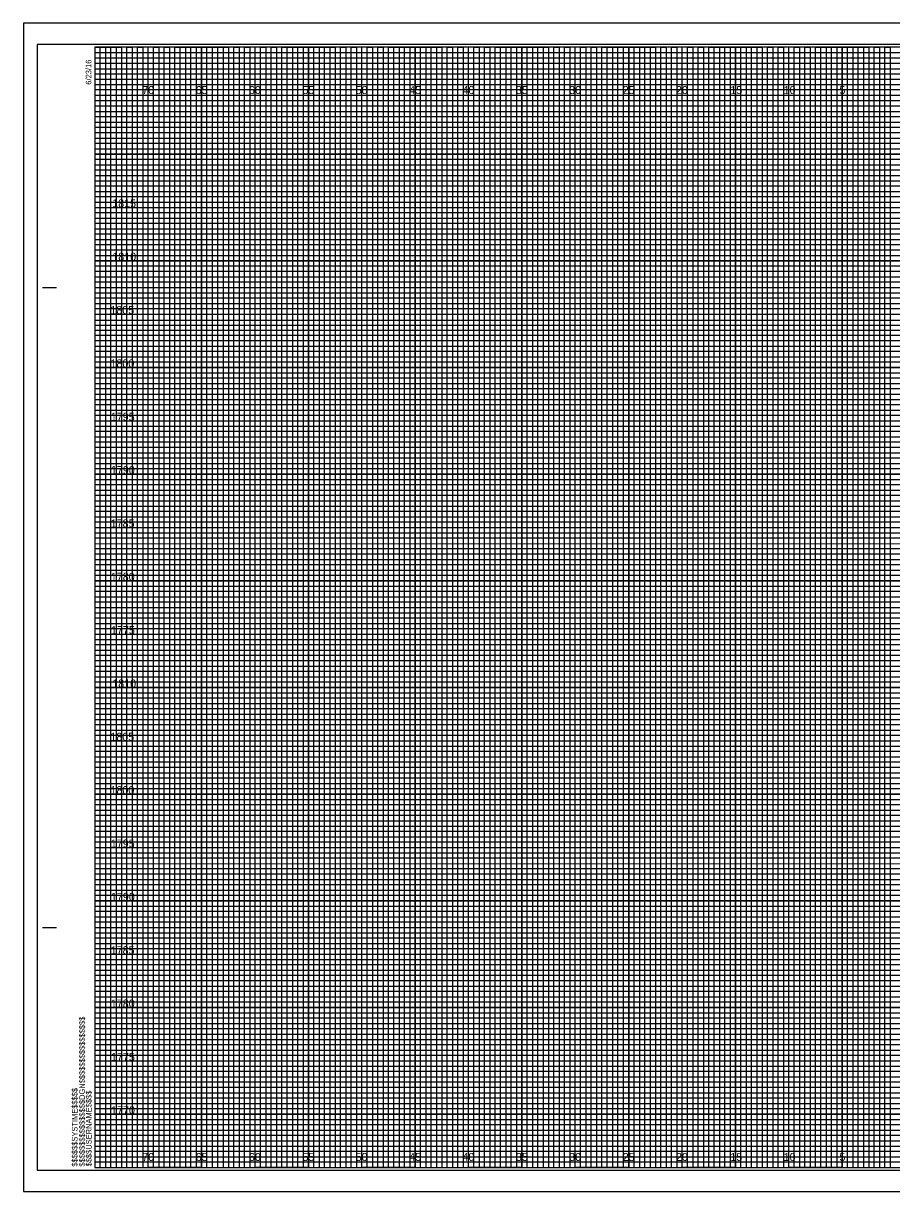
# Model space of a CAD drawing. Extents: x 346 to 514, y -13 to 537.
# Drawn here: x 346 to 427.4, y 207.2 to 316.7 of the extents above; entities that cross this region are included whole.
import ezdxf

# ---------------------------------------------------------------- set-up
doc = ezdxf.new("R2010")
doc.units = 0
for name, color, linetype in [('COGO Default Curve', 7, 'Continuous'), ('Prop Horizontal Alignment', 7, 'Continuous'), ('Prop XS DDE', 7, 'Continuous'), ('Scratch_Level_3', 7, 'Continuous'), ('Sheet Cross Section CELL', 7, 'Continuous'), ('Sheet Cross Section Grid Minor 1 CELL', 7, 'Continuous'), ('Sheet Cross Section Grid Minor 2 CELL', 7, 'Continuous'), ('Sheet Cutting Line CELL', 7, 'Continuous'), ('Sheet DOT Grid CELL', 7, 'Continuous'), ('Sheet Plot Border Inside CELL', 7, 'Continuous'), ('Sheet Plot Border Outside CELL', 7, 'Continuous')]:
    doc.layers.add(name, color=color, linetype=linetype)

msp = doc.modelspace()

# ---------------------------------------------------------------- linework, layer by layer
at = {"layer": 'COGO Default Curve'}
for points in [[(352.75, 314.43), (355.25, 314.43), (355.25, 209.43), (360.25, 209.43), (360.25, 314.43), (365.25, 314.43), (365.25, 209.43), (370.25, 209.43), (370.25, 314.43), (375.25, 314.43), (375.25, 209.43), (380.25, 209.43), (380.25, 314.43), (385.25, 314.43), (385.25, 209.43), (390.25, 209.43), (390.25, 314.43), (395.25, 314.43), (395.25, 209.43), (400.25, 209.43), (400.25, 314.43), (405.25, 314.43), (405.25, 209.43), (410.25, 209.43), (410.25, 314.43), (415.25, 314.43), (415.25, 209.43), (420.25, 209.43), (420.25, 314.43), (425.25, 314.43), (425.25, 209.43), (430.25, 209.43)], [(352.75, 311.93), (490.25, 311.93)], [(352.75, 301.93), (512.75, 301.93), (512.75, 306.93), (352.75, 306.93)], [(352.75, 291.93), (512.75, 291.93), (512.75, 296.93), (352.75, 296.93)], [(352.75, 281.93), (512.75, 281.93), (512.75, 286.93), (352.75, 286.93)], [(352.75, 271.93), (512.75, 271.93), (512.75, 276.93), (352.75, 276.93)], [(352.75, 261.93), (512.75, 261.93), (512.75, 266.93), (352.75, 266.93)], [(352.75, 251.93), (512.75, 251.93), (512.75, 256.93), (352.75, 256.93)], [(352.75, 241.93), (512.75, 241.93), (512.75, 246.93), (352.75, 246.93)], [(352.75, 231.93), (512.75, 231.93), (512.75, 236.93), (352.75, 236.93)], [(352.75, 221.93), (512.75, 221.93), (512.75, 226.93), (352.75, 226.93)], [(352.75, 211.93), (512.75, 211.93), (512.75, 216.93), (352.75, 216.93)]]:
    msp.add_lwpolyline(points, dxfattribs=at)
at = {"layer": 'Prop XS DDE'}
for p, q in [((357.75, 314.43), (352.75, 314.43)), ((357.75, 209.43), (357.75, 314.43)), ((367.75, 314.43), (362.75, 314.43)), ((362.75, 314.43), (362.75, 209.43)), ((367.75, 209.43), (367.75, 314.43)), ((377.75, 314.43), (372.75, 314.43)), ((372.75, 314.43), (372.75, 209.43)), ((377.75, 209.43), (377.75, 314.43)), ((387.75, 314.43), (382.75, 314.43)), ((382.75, 314.43), (382.75, 209.43)), ((387.75, 209.43), (387.75, 314.43)), ((397.75, 314.43), (392.75, 314.43)), ((392.75, 314.43), (392.75, 209.43)), ((397.75, 209.43), (397.75, 314.43)), ((407.75, 314.43), (402.75, 314.43)), ((402.75, 314.43), (402.75, 209.43)), ((407.75, 209.43), (407.75, 314.43)), ((417.75, 314.43), (412.75, 314.43)), ((412.75, 314.43), (412.75, 209.43)), ((417.75, 209.43), (417.75, 314.43)), ((427.75, 314.43), (422.75, 314.43)), ((422.75, 314.43), (422.75, 209.43)), ((362.75, 209.43), (357.75, 209.43)), ((372.75, 209.43), (367.75, 209.43)), ((382.75, 209.43), (377.75, 209.43)), ((392.75, 209.43), (387.75, 209.43)), ((402.75, 209.43), (397.75, 209.43)), ((412.75, 209.43), (407.75, 209.43)), ((422.75, 209.43), (417.75, 209.43))]:
    msp.add_line(p, q, dxfattribs=at)
for points in [[(352.75, 309.43), (512.75, 309.43), (512.75, 304.43), (352.75, 304.43)], [(352.75, 299.43), (512.75, 299.43), (512.75, 294.43), (352.75, 294.43)], [(352.75, 289.43), (512.75, 289.43), (512.75, 284.43), (352.75, 284.43)], [(352.75, 279.43), (512.75, 279.43), (512.75, 274.43), (352.75, 274.43)], [(352.75, 269.43), (512.75, 269.43), (512.75, 264.43), (352.75, 264.43)], [(352.75, 259.43), (512.75, 259.43), (512.75, 254.43), (352.75, 254.43)], [(352.75, 249.43), (512.75, 249.43), (512.75, 244.43), (352.75, 244.43)], [(352.75, 239.43), (512.75, 239.43), (512.75, 234.43), (352.75, 234.43)], [(352.75, 229.43), (512.75, 229.43), (512.75, 224.43), (352.75, 224.43)], [(352.75, 219.43), (512.75, 219.43), (512.75, 214.43), (352.75, 214.43)]]:
    msp.add_lwpolyline(points, dxfattribs=at)
at = {"layer": 'Sheet Cross Section CELL'}
for p, q in [((347.85, 291.93), (349.1, 291.93)), ((347.9, 291.93), (349.15, 291.93)), ((347.85, 231.93), (349.1, 231.93)), ((347.9, 231.93), (349.15, 231.93)), ((352.75, 209.43), (352.75, 209.43)), ((352.75, 209.43), (352.75, 209.43)), ((352.75, 209.43), (352.75, 209.43)), ((352.75, 209.43), (352.75, 209.43)), ((352.75, 209.43), (352.75, 209.43)), ((352.75, 209.43), (352.75, 209.43)), ((352.75, 209.43), (352.75, 209.43))]:
    msp.add_line(p, q, dxfattribs=at)
msp.add_lwpolyline([(512.75, 314.43), (352.75, 314.43), (352.75, 209.43), (512.75, 209.43)], close=True, dxfattribs=at)
at = {"layer": 'Sheet Cross Section Grid Minor 1 CELL'}
for p, q in [((352.75, 313.93), (482.75, 313.93)), ((482.75, 313.42), (352.75, 313.42)), ((352.75, 313.42), (352.75, 312.93)), ((352.75, 312.93), (482.75, 312.93)), ((482.75, 312.37), (352.75, 312.37)), ((352.75, 312.37), (352.75, 311.43)), ((352.75, 311.43), (512.75, 311.43))]:
    msp.add_line(p, q, dxfattribs=at)
for points in [[(352.75, 310.93), (487.75, 310.93), (512.75, 310.93), (512.75, 310.43), (352.75, 310.43)], [(352.75, 309.93), (512.75, 309.93), (512.75, 308.93), (352.75, 308.93)], [(352.75, 308.43), (512.75, 308.43), (512.75, 307.93), (352.75, 307.92)], [(352.75, 307.43), (512.75, 307.43), (512.75, 306.43), (352.75, 306.43)], [(352.75, 305.93), (512.75, 305.93), (512.75, 305.43), (352.75, 305.43)], [(352.75, 304.93), (512.75, 304.93), (512.75, 303.93), (352.75, 303.93)], [(352.75, 303.43), (512.75, 303.43), (512.75, 302.93), (352.75, 302.93)], [(352.75, 302.43), (512.75, 302.43), (512.75, 301.43), (352.75, 301.43)], [(352.75, 300.93), (512.75, 300.93), (512.75, 300.43), (352.75, 300.43)], [(352.75, 299.93), (512.75, 299.93), (512.75, 298.93), (352.75, 298.93)], [(352.75, 298.43), (512.75, 298.43), (512.75, 297.93), (352.75, 297.93)], [(352.75, 297.43), (512.75, 297.43), (512.75, 296.4), (512.75, 295.93), (512.75, 295.43), (352.75, 295.43)], [(352.75, 296.43), (512.75, 296.43), (512.75, 295.93), (352.75, 295.93)], [(352.75, 294.93), (512.75, 294.93), (512.75, 293.93), (352.75, 293.94)], [(352.75, 293.94), (512.75, 293.93), (512.75, 293.43), (352.75, 293.43)], [(352.75, 292.93), (512.75, 292.93), (512.75, 292.43), (352.75, 292.43)], [(352.75, 291.43), (512.75, 291.43), (512.75, 290.93), (352.75, 290.93)], [(352.75, 290.43), (512.75, 290.43), (512.75, 289.93), (352.75, 289.93)], [(352.71, 288.87), (512.75, 288.87), (512.75, 288.37), (352.71, 288.37)], [(352.75, 287.93), (512.75, 287.93), (512.75, 287.43), (352.75, 287.43)], [(352.75, 286.43), (512.75, 286.43), (512.75, 285.93), (352.75, 285.93)], [(352.75, 285.43), (512.75, 285.43), (512.75, 284.93), (352.75, 284.93)], [(352.75, 283.93), (512.75, 283.93), (512.75, 283.43), (352.75, 283.43)], [(352.75, 282.93), (512.75, 282.93), (512.75, 282.43), (352.75, 282.43)], [(352.75, 281.43), (512.75, 281.43), (512.75, 280.93), (352.75, 280.93)], [(352.75, 280.43), (512.75, 280.43), (512.75, 279.93), (352.75, 279.93)], [(352.75, 278.93), (512.75, 278.93), (512.74, 278.42), (352.75, 278.43)], [(352.75, 277.93), (512.75, 277.93), (512.75, 277.43), (352.75, 277.43)], [(352.75, 276.43), (512.75, 276.43), (512.75, 275.93), (352.75, 275.93)], [(352.75, 275.43), (512.75, 275.43), (512.75, 274.93), (352.75, 274.93)], [(352.75, 273.93), (512.75, 273.93), (512.75, 273.43), (352.75, 273.43)], [(352.75, 272.93), (512.75, 272.93), (512.75, 272.43), (352.75, 272.43)], [(352.75, 271.43), (512.75, 271.43), (512.75, 270.93), (352.75, 270.93)], [(352.75, 270.43), (512.75, 270.43), (512.75, 269.93), (352.75, 269.93)], [(352.75, 268.93), (512.75, 268.93), (512.75, 268.43), (352.75, 268.43)], [(352.75, 267.92), (512.78, 267.88), (512.75, 267.43), (352.75, 267.43)], [(352.75, 266.43), (512.75, 266.43), (512.75, 265.93), (352.75, 265.93)], [(352.75, 265.43), (512.75, 265.43), (512.75, 264.93), (352.75, 264.93)], [(352.75, 263.93), (512.75, 263.93), (512.75, 263.43), (352.75, 263.43)], [(352.75, 262.93), (512.75, 262.93), (512.75, 262.43), (352.75, 262.43)], [(352.75, 261.43), (512.75, 261.43), (512.75, 260.93), (352.75, 260.93)], [(352.75, 260.43), (512.75, 260.43), (512.75, 259.93), (352.75, 259.93)], [(352.75, 258.93), (512.75, 258.93), (512.75, 258.43), (352.75, 258.43)], [(352.75, 257.93), (512.75, 257.93), (512.75, 257.43), (352.75, 257.43)], [(352.75, 256.43), (512.75, 256.43), (512.75, 255.93), (352.75, 255.93)], [(352.75, 255.43), (512.75, 255.43), (512.75, 254.93), (352.75, 254.93)], [(352.75, 253.93), (512.75, 253.93), (512.75, 253.43), (352.75, 253.43)], [(352.75, 252.93), (512.75, 252.93), (512.75, 252.43), (352.75, 252.43)], [(352.75, 251.43), (512.75, 251.43), (512.75, 250.93), (352.75, 250.93)], [(352.75, 250.43), (512.75, 250.43), (512.75, 249.93), (352.75, 249.93)], [(352.75, 248.93), (512.75, 248.93), (512.74, 248.42), (352.75, 248.43)], [(352.75, 247.93), (512.75, 247.93), (512.75, 247.43), (352.75, 247.43)], [(352.75, 246.43), (512.75, 246.43), (512.75, 245.93), (352.75, 245.93)], [(352.75, 245.43), (512.75, 245.43), (512.75, 244.93), (352.75, 244.93)], [(352.75, 243.93), (512.75, 243.93), (512.75, 243.43), (352.75, 243.43)], [(352.75, 242.93), (512.75, 242.93), (512.75, 242.43), (352.75, 242.43)], [(352.75, 241.43), (512.75, 241.43), (512.75, 240.93), (352.75, 240.93)], [(352.75, 240.43), (512.75, 240.43), (512.75, 239.93), (352.75, 239.93)], [(352.75, 238.93), (512.75, 238.93), (512.75, 238.43), (352.75, 238.43)], [(352.75, 237.92), (512.78, 237.88), (512.75, 237.43), (352.75, 237.43)], [(352.75, 236.43), (512.75, 236.43), (512.75, 235.93), (352.75, 235.93)], [(352.75, 235.43), (512.75, 235.43), (512.75, 234.93), (352.75, 234.93)], [(352.75, 233.93), (512.75, 233.93), (512.75, 233.43), (352.75, 233.43)], [(352.75, 232.93), (512.75, 232.93), (512.75, 232.43), (352.75, 232.43)], [(352.75, 231.43), (512.75, 231.43), (512.75, 230.93), (352.75, 230.93)], [(352.75, 230.43), (512.75, 230.43), (512.75, 229.93), (352.75, 229.93)], [(352.75, 228.93), (512.75, 228.93), (512.75, 228.43), (352.75, 228.43)], [(352.75, 227.93), (512.75, 227.93), (512.75, 227.43), (352.75, 227.43)], [(352.75, 226.43), (512.75, 226.43), (512.75, 225.93), (352.75, 225.93)], [(352.75, 225.43), (512.75, 225.43), (512.75, 224.93), (352.75, 224.93)], [(352.75, 223.93), (512.75, 223.93), (512.75, 223.43), (352.75, 223.43)], [(352.75, 222.93), (512.75, 222.93), (512.75, 222.43), (352.75, 222.43)], [(352.75, 221.43), (512.75, 221.43), (512.75, 220.93), (352.75, 220.93)], [(352.75, 220.43), (512.75, 220.43), (512.75, 219.93), (352.75, 219.93)], [(352.75, 218.93), (512.75, 218.93), (512.75, 218.43), (352.75, 218.43)], [(352.75, 217.93), (512.75, 217.93), (512.75, 217.43), (352.75, 217.43)], [(352.75, 216.43), (512.75, 216.43), (512.75, 215.93), (352.75, 215.93)], [(352.75, 215.43), (512.75, 215.43), (512.75, 214.93), (352.75, 214.93)], [(352.75, 213.93), (512.75, 213.93), (512.75, 213.43), (352.75, 213.43)], [(352.75, 212.93), (512.75, 212.93), (512.75, 212.43), (352.75, 212.43)], [(352.75, 211.43), (512.75, 211.43), (512.75, 210.93), (352.75, 210.93)], [(352.75, 210.43), (512.75, 210.43), (512.75, 209.93), (352.75, 209.93)]]:
    msp.add_lwpolyline(points, dxfattribs=at)
at = {"layer": 'Sheet Cross Section Grid Minor 2 CELL'}
for points in [[(352.75, 209.43), (353.25, 209.43), (353.25, 314.43), (353.75, 314.43), (353.75, 209.43)], [(353.75, 209.43), (354.25, 209.43), (354.25, 314.43), (354.75, 314.43), (354.75, 209.43)], [(355.25, 209.43), (355.75, 209.43), (355.75, 314.43), (356.25, 314.43), (356.25, 209.43)], [(356.25, 209.43), (356.75, 209.43), (356.75, 314.43), (357.25, 314.43), (357.25, 209.43)], [(357.75, 209.43), (358.25, 209.43), (358.25, 314.43), (358.75, 314.43), (358.75, 209.43)], [(358.75, 209.43), (359.25, 209.43), (359.25, 314.43), (359.75, 314.43), (359.75, 209.43)], [(360.25, 209.43), (360.75, 209.43), (360.75, 314.43), (361.25, 314.43), (361.25, 209.43)], [(361.25, 209.43), (361.75, 209.43), (361.75, 314.43), (362.25, 314.43), (362.25, 209.43)], [(362.75, 209.43), (363.25, 209.43), (363.25, 314.43), (363.75, 314.43), (363.75, 209.43)], [(363.75, 209.43), (364.25, 209.43), (364.25, 314.43), (364.75, 314.43), (364.75, 209.43)], [(365.25, 209.43), (365.75, 209.43), (365.75, 314.43), (366.25, 314.43), (366.25, 209.43)], [(366.25, 209.43), (366.75, 209.43), (366.75, 314.43), (367.25, 314.43), (367.25, 209.43)], [(367.75, 209.43), (368.25, 209.43), (368.25, 314.43), (368.75, 314.43), (368.75, 209.43)], [(368.75, 209.43), (369.25, 209.43), (369.25, 314.43), (369.75, 314.43), (369.75, 209.43)], [(370.25, 209.43), (370.75, 209.43), (370.75, 314.43), (371.25, 314.43), (371.25, 209.43)], [(371.25, 209.43), (371.75, 209.43), (371.75, 314.43), (372.25, 314.43), (372.25, 209.43)], [(372.75, 209.43), (373.25, 209.43), (373.25, 314.43), (373.75, 314.43), (373.75, 209.43)], [(373.75, 209.43), (374.25, 209.43), (374.25, 314.43), (374.75, 314.43), (374.75, 209.43)], [(375.25, 209.43), (375.75, 209.43), (375.75, 314.43), (376.25, 314.43), (376.25, 209.43)], [(376.25, 209.43), (376.75, 209.43), (376.75, 314.43), (377.25, 314.43), (377.25, 209.43)], [(377.75, 209.43), (378.25, 209.43), (378.25, 314.43), (378.75, 314.43), (378.75, 209.43)], [(378.75, 209.43), (379.25, 209.43), (379.25, 314.43), (379.75, 314.43), (379.75, 209.43)], [(380.25, 209.43), (380.75, 209.43), (380.75, 314.43), (381.25, 314.43), (381.25, 209.43)], [(381.25, 209.43), (381.75, 209.43), (381.75, 314.43), (382.25, 314.43), (382.25, 209.43)], [(382.75, 209.43), (383.25, 209.43), (383.25, 314.43), (383.75, 314.43), (383.75, 209.43)], [(383.75, 209.43), (384.25, 209.43), (384.25, 314.43), (384.75, 314.43), (384.75, 209.43)], [(385.25, 209.43), (385.75, 209.43), (385.75, 314.43), (386.25, 314.43), (386.25, 209.43)], [(386.25, 209.43), (386.75, 209.43), (386.75, 314.43), (387.25, 314.43), (387.25, 209.43)], [(387.75, 209.43), (388.25, 209.43), (388.25, 314.43), (388.75, 314.43), (388.75, 209.43)], [(388.75, 209.43), (389.25, 209.43), (389.25, 314.43), (389.75, 314.43), (389.75, 209.43)], [(390.25, 209.43), (390.75, 209.43), (390.75, 314.43), (391.25, 314.43), (391.25, 209.43)], [(391.25, 209.43), (391.75, 209.43), (391.75, 314.43), (392.25, 314.43), (392.25, 209.43)], [(392.75, 209.43), (393.25, 209.43), (393.25, 314.43), (393.75, 314.43), (393.75, 209.43)], [(393.75, 209.43), (394.25, 209.43), (394.25, 314.43), (394.75, 314.43), (394.75, 209.43)], [(395.25, 209.43), (395.75, 209.43), (395.75, 314.43), (396.25, 314.43), (396.25, 209.43)], [(396.25, 209.43), (396.75, 209.43), (396.75, 314.43), (397.25, 314.43), (397.25, 209.43)], [(397.75, 209.43), (398.25, 209.43), (398.25, 314.43), (398.75, 314.43), (398.75, 209.43)], [(398.75, 209.43), (399.25, 209.43), (399.25, 314.43), (399.75, 314.43), (399.75, 209.43)], [(400.25, 209.43), (400.75, 209.43), (400.75, 314.43), (401.25, 314.43), (401.25, 209.43)], [(401.25, 209.43), (401.75, 209.43), (401.75, 314.43), (402.25, 314.43), (402.25, 209.43)], [(402.75, 209.43), (403.25, 209.43), (403.25, 314.43), (403.75, 314.43), (403.75, 209.43)], [(403.75, 209.43), (404.25, 209.43), (404.25, 314.43), (404.75, 314.43), (404.75, 209.43)], [(405.25, 209.43), (405.75, 209.43), (405.75, 314.43), (406.25, 314.43), (406.25, 209.43)], [(406.25, 209.43), (406.75, 209.43), (406.75, 314.43), (407.25, 314.43), (407.25, 209.43)], [(407.75, 209.43), (408.25, 209.43), (408.25, 314.43), (408.75, 314.43), (408.75, 209.43)], [(408.75, 209.43), (409.25, 209.43), (409.25, 314.43), (409.75, 314.43), (409.75, 209.43)], [(410.25, 209.43), (410.75, 209.43), (410.75, 314.43), (411.25, 314.43), (411.25, 209.43)], [(411.25, 209.43), (411.75, 209.43), (411.75, 314.43), (412.25, 314.43), (412.25, 209.43)], [(412.75, 209.43), (413.25, 209.43), (413.25, 314.43), (413.75, 314.43), (413.75, 209.43)], [(413.75, 209.43), (414.25, 209.43), (414.25, 314.43), (414.75, 314.43), (414.75, 209.43)], [(415.25, 209.43), (415.75, 209.43), (415.75, 314.43), (416.25, 314.43), (416.25, 209.43)], [(416.25, 209.43), (416.75, 209.43), (416.75, 314.43), (417.25, 314.43), (417.25, 209.43)], [(417.75, 209.43), (418.25, 209.43), (418.25, 314.43), (418.75, 314.43), (418.75, 209.43)], [(418.75, 209.43), (419.25, 209.43), (419.25, 314.43), (419.75, 314.43), (419.75, 209.43)], [(420.25, 209.43), (420.75, 209.43), (420.75, 314.43), (421.25, 314.43), (421.25, 209.43)], [(421.25, 209.43), (421.75, 209.43), (421.75, 314.43), (422.25, 314.43), (422.25, 209.43)], [(422.75, 209.43), (423.25, 209.43), (423.25, 314.43), (423.75, 314.43), (423.75, 209.43)], [(423.75, 209.43), (424.25, 209.43), (424.25, 314.43), (424.75, 314.43), (424.75, 209.43)], [(425.25, 209.43), (425.75, 209.43), (425.75, 314.43), (426.25, 314.43), (426.25, 209.43)], [(426.25, 209.43), (426.75, 209.43), (426.75, 314.43), (427.25, 314.43), (427.25, 209.43)]]:
    msp.add_lwpolyline(points, dxfattribs=at)
at = {"layer": 'Sheet Cutting Line CELL'}
for p, q in [((514.4, 316.68), (346.05, 316.68)), ((346.05, 316.68), (346.05, 207.18)), ((346.05, 207.18), (514.4, 207.18))]:
    msp.add_line(p, q, dxfattribs=at)
at = {"layer": 'Sheet DOT Grid CELL'}
for p, q in [((357.75, 209.43), (357.75, 314.43)), ((362.75, 209.43), (362.75, 314.43)), ((367.75, 209.43), (367.75, 314.43)), ((372.75, 209.43), (372.75, 314.43)), ((377.75, 209.43), (377.75, 314.43)), ((382.75, 209.43), (382.75, 314.43)), ((387.75, 209.43), (387.75, 314.43)), ((392.75, 209.43), (392.75, 314.43)), ((397.75, 209.43), (397.75, 314.43)), ((402.75, 209.43), (402.75, 314.43)), ((407.75, 209.43), (407.75, 314.43)), ((412.75, 209.43), (412.75, 314.43)), ((417.75, 209.43), (417.75, 314.43)), ((422.75, 209.43), (422.75, 314.43)), ((352.75, 309.43), (512.75, 309.43)), ((352.75, 304.43), (512.75, 304.43)), ((352.75, 299.43), (512.75, 299.43)), ((352.75, 294.43), (512.75, 294.43)), ((352.75, 289.43), (512.75, 289.43)), ((352.75, 284.43), (512.75, 284.43)), ((352.75, 279.43), (512.75, 279.43)), ((352.75, 274.43), (512.75, 274.43)), ((352.75, 269.43), (512.75, 269.43)), ((352.75, 264.43), (512.75, 264.43)), ((352.75, 259.43), (512.75, 259.43)), ((352.75, 254.43), (512.75, 254.43)), ((352.75, 249.43), (512.75, 249.43)), ((352.75, 244.43), (512.75, 244.43)), ((352.75, 239.43), (512.75, 239.43)), ((352.75, 234.43), (512.75, 234.43)), ((352.75, 229.43), (512.75, 229.43)), ((352.75, 224.43), (512.75, 224.43)), ((352.75, 219.43), (512.75, 219.43)), ((352.75, 214.43), (512.75, 214.43))]:
    msp.add_line(p, q, dxfattribs=at)
at = {"layer": 'Sheet Plot Border Inside CELL'}
msp.add_lwpolyline([(347.35, 209.18), (513.95, 209.18), (513.95, 314.68), (347.35, 314.68)], close=True, dxfattribs=at)
at = {"layer": 'Sheet Plot Border Outside CELL'}
msp.add_lwpolyline([(346.05, 207.18), (514.4, 207.18), (514.4, 316.68), (346.05, 316.68)], close=True, dxfattribs=at)

# ---------------------------------------------------------------- texts
at = {"layer": 'Prop Horizontal Alignment'}
for s, p in [('1815', (354.37, 299.43)), ('1810', (354.38, 294.43)), ('1805', (354.2, 289.43)), ('1800', (354.21, 284.43)), ('1795', (354.24, 279.43)), ('1790', (354.25, 274.43)), ('1785', (354.23, 269.43)), ('1780', (354.24, 264.43)), ('1775', (354.26, 259.43)), ('1810', (354.38, 254.43)), ('1805', (354.2, 249.43)), ('1800', (354.21, 244.43)), ('1795', (354.24, 239.43)), ('1790', (354.25, 234.43)), ('1785', (354.23, 229.43)), ('1780', (354.24, 224.43)), ('1775', (354.26, 219.43)), ('1770', (354.27, 214.43))]:
    msp.add_text(s, height=0.75, dxfattribs=at).set_placement(p)
at = {"layer": 'Scratch_Level_3'}
for s, p in [('70', (357.18, 310.05)), ('65', (362.19, 310.05)), ('60', (367.18, 310.05)), ('55', (372.19, 310.05)), ('50', (377.18, 310.05)), ('45', (382.19, 310.05)), ('40', (387.18, 310.05)), ('35', (392.19, 310.05)), ('30', (397.18, 310.05)), ('25', (402.19, 310.05)), ('20', (407.18, 310.05)), ('15', (412.28, 310.05)), ('10', (417.27, 310.05)), ('5', (422.49, 310.05)), ('70', (357.18, 210.05)), ('65', (362.19, 210.05)), ('60', (367.18, 210.05)), ('55', (372.19, 210.05)), ('50', (377.18, 210.05)), ('45', (382.19, 210.05)), ('40', (387.18, 210.05)), ('35', (392.19, 210.05)), ('30', (397.18, 210.05)), ('25', (402.19, 210.05)), ('20', (407.18, 210.05)), ('15', (412.28, 210.05)), ('10', (417.27, 210.05)), ('5', (422.49, 210.05))]:
    msp.add_text(s, height=0.75, dxfattribs=at).set_placement(p)
at = {"layer": 'Sheet Cross Section CELL'}
for s, p in [('6/23/16', (352.42, 310.93)), ('$$$$$$$$$$$$$$$$DGN$$$$$$$$$$$$$$$$', (351.81, 209.52)), ('$$$$$$SYSTIME$$$$$', (351.12, 209.52)), ('$$$$USERNAME$$$$', (352.44, 209.54))]:
    msp.add_text(s, height=0.525, rotation=90, dxfattribs=at).set_placement(p)

doc.saveas('drawing.dxf')
